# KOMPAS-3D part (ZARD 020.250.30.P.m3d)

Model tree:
1. Плоскость XY
2. Плоскость ZX
3. Плоскость ZY
4. Ось X
5. Ось Y
6. Ось Z
7. Начало координат
8. Смещенная плоскость:1
     Расстояние = 107
9. Смещенная плоскость:2
     Расстояние = 107
10. Булева операция:1
11. Булева операция:2
12. Булева операция:4
13. Булева операция:5
14. Булева операция:6
15. Булева операция:7
